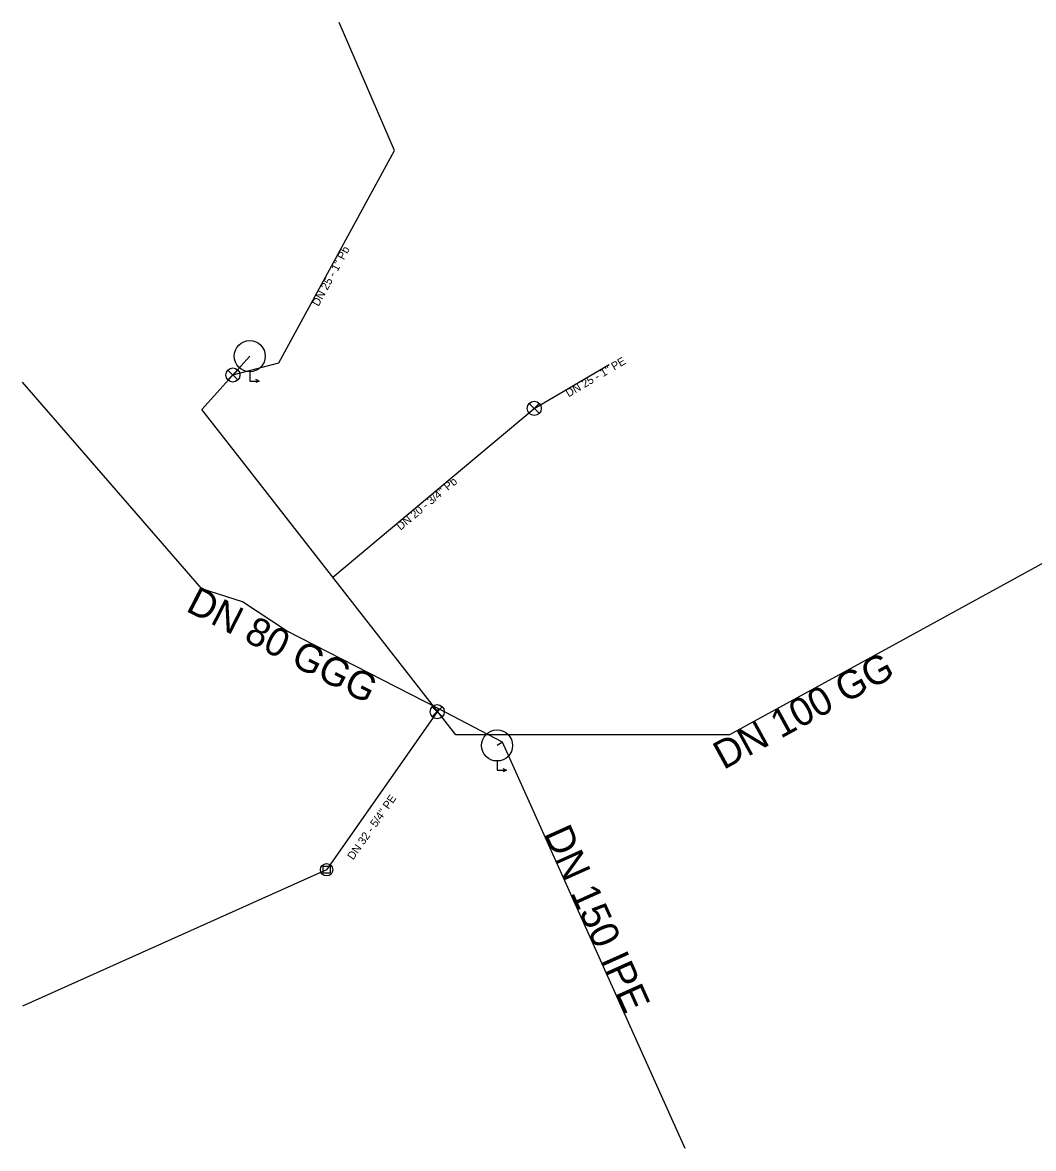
# Model space of a CAD drawing. Extents: x -483822 to -483707, y -1128589 to -1128518.
# Drawn here: x -483822.1 to -483764.7, y -1128589.2 to -1128525.2 of the extents above; entities that cross this region are included whole.
import ezdxf

# ---------------------------------------------------------------- set-up
doc = ezdxf.new("R2010")
doc.units = 0
for name, color, linetype in [('_hydrantova_odbocka_', 7, 'Continuous'), ('_pripojka_priblizne_', 7, 'Continuous'), ('_voda_smvak_prevzato_z_dokumentace_', 7, 'Continuous'), ('_vodovodni_chranicka_', 7, 'Continuous'), ('Default', 7, 'Continuous'), ('MoLevel 28', 7, 'Continuous'), ('MoLevel 30', 7, 'Continuous'), ('MoLevel 32', 7, 'Continuous'), ('MoLevel 42', 7, 'Continuous'), ('MoLevel 46', 7, 'Continuous'), ('MoLevel 53', 7, 'Continuous'), ('MoLevel 60', 7, 'Continuous')]:
    doc.layers.add(name, color=color, linetype=linetype)

# ---------------------------------------------------------------- blocks, each defined once
blk = doc.blocks.new('_uzaver_pripojka_')
at = {"layer": 'Default'}
for p, q in [((-0.000035, -0.000035), (0.000035, 0.000035)), ((0.000035, -0.000035), (-0.000035, 0.000035))]:
    blk.add_line(p, q, dxfattribs=at)
for radius in [0.00005, 0.0000025]:
    blk.add_circle((0, 0), radius, dxfattribs=at)
blk = doc.blocks.new('_hydrant_voda_')
at = {"layer": 'Default'}
blk.add_line((0.00003, -0.00008), (0.00002, -0.000085), dxfattribs=at)
blk.add_lwpolyline([(0, -0.00005), (0, -0.00008), (0.00003, -0.00008), (0.00002, -0.000075)], dxfattribs=at)
blk.add_circle((0, 0), 0.00005, dxfattribs=at)
blk = doc.blocks.new('_sachta_voda_')
at = {"layer": 'Default'}
blk.add_circle((0, 0), 0.000035, dxfattribs=at)
blk = doc.blocks.new('_poklop_voda_')
at = {"layer": 'Default'}
blk.add_lwpolyline([(-0.00002, 0.00002), (0.00002, 0.00002), (0.00002, -0.00002), (-0.00002, -0.00002), (-0.00002, 0.00002)], dxfattribs=at)

msp = doc.modelspace()

# ---------------------------------------------------------------- linework, layer by layer
at = {"layer": '_hydrantova_odbocka_'}
msp.add_line((-483794.82, -1128566.07), (-483795.13, -1128566.26), dxfattribs=at)
at = {"layer": '_pripojka_priblizne_'}
for p, q in [((-483810.136, -1128545.203), (-483807.518, -1128544.521)), ((-483793.015, -1128547.1), (-483788.764, -1128544.598)), ((-483796.981, -1128550.424), (-483793.015, -1128547.1)), ((-483804.464, -1128556.694), (-483796.981, -1128550.424)), ((-483804.81, -1128573.32), (-483822.088, -1128581.079))]:
    msp.add_line(p, q, dxfattribs=at)
for points in [[(-483807.518, -1128544.521), (-483800.958, -1128532.451), (-483804.1, -1128525.17)], [(-483798.48, -1128564.16), (-483798.53, -1128564.34), (-483804.81, -1128573.32), (-483804.81, -1128573.32)]]:
    msp.add_lwpolyline(points, dxfattribs=at)
at = {"layer": '_voda_smvak_prevzato_z_dokumentace_'}
for p, q in [((-483811.894, -1128547.165), (-483809.179, -1128544.134)), ((-483811.9, -1128557.36), (-483822.088, -1128545.602)), ((-483784.445, -1128589.165), (-483794.82, -1128566.07))]:
    msp.add_line(p, q, dxfattribs=at)
for points in [[(-483735.932, -1128542.704), (-483751.684, -1128549.998), (-483762.419, -1128554.968), (-483772.473, -1128560.474), (-483781.93, -1128565.654), (-483797.478, -1128565.654), (-483809.647, -1128550.046), (-483811.894, -1128547.165)], [(-483794.82, -1128566.07), (-483798.48, -1128564.16), (-483807.1, -1128559.74), (-483809.59, -1128558.09), (-483811.9, -1128557.36)]]:
    msp.add_lwpolyline(points, dxfattribs=at)
at = {"layer": '_vodovodni_chranicka_'}
msp.add_line((-483784.445, -1128589.165), (-483794.82, -1128566.07), dxfattribs=at)

# ---------------------------------------------------------------- block references
at = {"layer": 'MoLevel 28', "xscale": 17636.68430335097, "yscale": 17636.68430335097}
for p in [(-483809.179, -1128544.134), (-483795.13, -1128566.26)]:
    msp.add_blockref('_hydrant_voda_', p, dxfattribs=at)
at = {"layer": 'MoLevel 30', "xscale": 10000, "yscale": 10000}
msp.add_blockref('_sachta_voda_', (-483804.81, -1128573.32), dxfattribs=at)
at = {"layer": 'MoLevel 42', "xscale": 10000, "yscale": 10000}
msp.add_blockref('_poklop_voda_', (-483804.81, -1128573.32), dxfattribs=at)
at = {"layer": 'MoLevel 53', "xscale": 7999.999999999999, "yscale": 7999.999999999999}
for p in [(-483810.136, -1128545.203), (-483793.015, -1128547.1), (-483798.53, -1128564.34)]:
    msp.add_blockref('_uzaver_pripojka_', p, dxfattribs=at)

# ---------------------------------------------------------------- texts
at = {"layer": 'MoLevel 32'}
for s, rotation, p in [("DN 25 - 1'' Pb", 61.47466, (-483805.27, -1128541.337)), ("DN 25 - 1'' PE", 30.49024, (-483791.063, -1128546.479)), ("DN 20 - 3/4'' Pb", 39.96071, (-483800.61, -1128554.059)), ("DN 32 - 5/4'' PE", 55.03443, (-483803.302, -1128572.798))]:
    msp.add_text(s, height=0.455, rotation=rotation, dxfattribs=at).set_placement(p)
at = {"layer": 'MoLevel 46'}
for s, rotation, p in [('DN 80 GGG', 332.85302, (-483812.868, -1128558.586)), ('DN 100 GG', 28.71139, (-483782.259, -1128567.664))]:
    msp.add_text(s, height=1.6049, rotation=rotation, dxfattribs=at).set_placement(p)
at = {"layer": 'MoLevel 60'}
msp.add_text('DN 150 IPE', height=1.6049, rotation=294.19102, dxfattribs=at).set_placement((-483792.491, -1128571.255))

doc.saveas('drawing.dxf')
